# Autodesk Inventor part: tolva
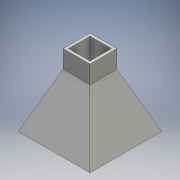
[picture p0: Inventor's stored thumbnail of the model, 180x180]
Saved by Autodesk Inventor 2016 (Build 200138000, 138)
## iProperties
Created: 2016-06
Part Number: tolva
Material: Genérico
Document SubType Name: Modeling
Designer: adm
Density: 1 g/cm^3
Appearance: Valor por defecto
Author: adm
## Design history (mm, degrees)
sketch "Boceto1"
  geometry: L1 (-40, -40)-(40, -40); L2 (40, -40)-(40, 40); L3 (40, 40)-(-40, 40); L4 (-40, 40)-(-40, -40); L5 (-40, -40)-(40, 40); L6 (40, -40)-(-40, 40); 1 further point
  constraints: 12 end point, 2 midpoint, 2 parallel, 1 horizontal, 1 perpendicular
  dimensions: "d0" = 80 distance of L3.end L2.end; "d1" = 80 distance of L2.end L1.end
node "Plano de trabajo1"
sketch "Boceto2"
  geometry: L1 (-15, -15)-(15, -15); L2 (15, -15)-(15, 15); L3 (15, 15)-(-15, 15); L4 (-15, 15)-(-15, -15); L5 (-15, -15)-(15, 15); L6 (15, -15)-(-15, 15); 1 further point
  constraints: 12 end point, 2 midpoint, 2 parallel, 1 horizontal, 1 perpendicular
  dimensions: "d3" = 30 distance of L3.end L2.end; "d4" = 30 distance of L2.end L1.end
feature "Solevación1" sketch "Boceto2" dims "d5" = 0, "d6" = 90 deg, "d7" = 0, "d8" = 90 deg
sketch "Boceto3"
  geometry: L1 (30, 30)-(0, 30) reference; L2 (0, 0)-(30, 0); L3 (30, 0)-(30, 30); L4 (30, 30)-(0, 30); L5 (0, 30)-(0, 0); L6 (0, 0)-(30, 30); L7 (30, 0)-(0, 30); 1 further point
  constraints: 12 end point, 2 midpoint, 2 parallel, 1 horizontal, 1 perpendicular
  dimensions: "d9" = 30 distance of L4.end L1.start (derived); "d10" = 30 distance of L1.start L2.end (derived)
extrude "Extrusión1" join sketch "Boceto3" distance "d11" = 20; taper "d12" = 0 deg
feature "Vaciado1" dims "d13" = 3
node "Sólido1"
